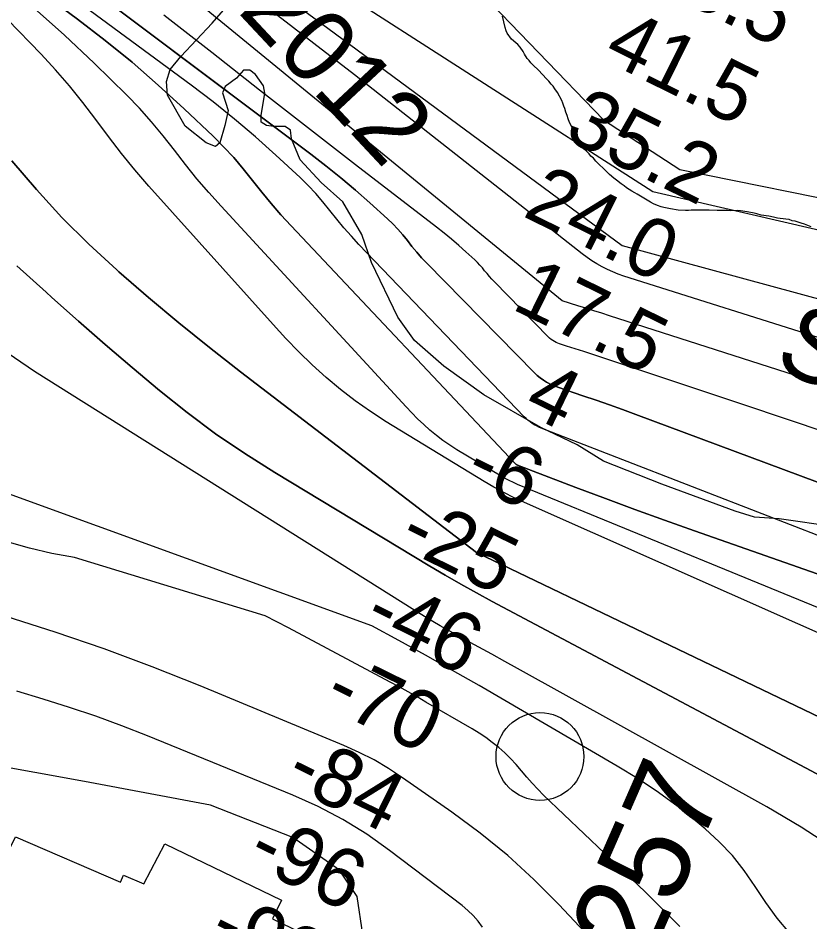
# Model space of a CAD drawing. Extents: x 3263578 to 3301413, y 764927 to 798602.
# Drawn here: x 3281967 to 3282869, y 784025 to 785055 of the extents above; entities that cross this region are included whole.
import ezdxf

# ---------------------------------------------------------------- set-up
doc = ezdxf.new("R2010")
doc.units = 0
for name, color, linetype in [('V-RIVR-EDGE', 7, 'Continuous'), ('V-RIVR-IDEN', 7, 'Continuous'), ('V-RIVR-MILE', 7, 'Continuous'), ('V-RIVR-RANG', 7, 'Continuous'), ('V-RRAP-RVMT', 7, 'Continuous'), ('V-SITE-VEGE', 7, 'Continuous'), ('V-TOPO-DPTH', 7, 'Continuous'), ('V-TOPO-MAJR', 7, 'Continuous'), ('V-TOPO-MINR', 7, 'Continuous'), ('V-TOPO-WATR', 7, 'Continuous')]:
    doc.layers.add(name, color=color, linetype=linetype)

msp = doc.modelspace()

# ---------------------------------------------------------------- linework, layer by layer
at = {"layer": 'V-RIVR-EDGE'}
msp.add_lwpolyline([(3282896.9, 784475.3), (3282833.4, 784484.6), (3282805.6, 784486.4), (3282783.5, 784493), (3282700.1, 784524), (3282633.6, 784550.3), (3282603.7, 784568.6), (3282562, 784588.3), (3282497.3, 784625.8), (3282451.8, 784658.5), (3282418.4, 784687.7), (3282399.3, 784714.3), (3282369.5, 784776.5), (3282358.3, 784808.3), (3282336.6, 784845.7), (3282311.9, 784867.5), (3282288, 784893.2), (3282278.1, 784917.2), (3282277.3, 784927.2), (3282271.2, 784931.5), (3282258.1, 784931.5), (3282249.9, 784932.4), (3282243.8, 784936.4), (3282243.8, 784943.8), (3282247.8, 784969.4), (3282246.5, 784977.7), (3282237.4, 784990.7), (3282230.9, 784995.5), (3282223.5, 784995.5), (3282215.7, 784986.4), (3282202.6, 784976.9), (3282199.6, 784969.5), (3282206, 784949.5), (3282202.5, 784932.6), (3282196.8, 784912.6), (3282191.6, 784908.7), (3282181.2, 784912.6), (3282157.3, 784931.8), (3282137, 784967.1), (3282136.1, 784982.7), (3282140.1, 784996.2), (3282152.3, 785010.9), (3282188, 785049.1), (3282216.8, 785082.5)], dxfattribs=at)
at = {"layer": 'V-RIVR-MILE'}
msp.add_circle((3282561.2, 784213.7), 50, dxfattribs=at)
at = {"layer": 'V-RRAP-RVMT'}
msp.add_lwpolyline([(3281527, 784176.8), (3281659.2, 784111.8), (3281678.1, 784148.8), (3281803, 784083.6), (3281841.2, 784155.5), (3281953.1, 784099.7), (3281963.9, 784122.4), (3282083.6, 784070.4), (3282087.1, 784078.4), (3282110.2, 784068.8), (3282133.9, 784114.1), (3282266.9, 784050.1), (3282256.8, 784028.8), (3282374.6, 783971.7), (3282287.6, 783777.8), (3282370.5, 783940), (3282499.2, 783875.4), (3282489.6, 783855.9)], dxfattribs=at)
at = {"layer": 'V-SITE-VEGE'}
for points in [[(3282598.1, 784929.3), (3282595, 784936), (3282593.3, 784940.1), (3282592, 784944), (3282590.5, 784947.6), (3282589.6, 784951.7), (3282588.4, 784954.5), (3282587.3, 784958), (3282586.2, 784960.9), (3282581.1, 784969.9), (3282578.2, 784974.2), (3282576.1, 784977.1), (3282573.9, 784979.5), (3282571.2, 784983), (3282568.8, 784985.7), (3282559.4, 784995.4), (3282553.5, 785001.2), (3282550.9, 785003.9), (3282548.8, 785006.4), (3282546.8, 785008.9), (3282543.5, 785013.8), (3282542.2, 785016.6), (3282538.5, 785021.8), (3282536.1, 785024.7), (3282533.7, 785026.7), (3282528.8, 785030.7), (3282523.9, 785037.5), (3282522.8, 785040.3), (3282521.7, 785044), (3282518.4, 785057)], [(3282869.9, 784817.1), (3282862.5, 784820), (3282858.7, 784821.3), (3282851.7, 784823.3), (3282848.4, 784823.9), (3282844.9, 784825.4), (3282841, 784825.7), (3282831.8, 784826.8), (3282827.2, 784827.9), (3282821.7, 784829.1), (3282813.1, 784830.5), (3282808.3, 784832), (3282805.3, 784832.7), (3282797.1, 784834.3), (3282789.6, 784835.3), (3282786.6, 784835.6), (3282777.7, 784835.4), (3282774.7, 784835.7), (3282770.3, 784835.8), (3282762.8, 784835.6), (3282753.9, 784836.2), (3282750.5, 784836.1), (3282746.7, 784836.2), (3282743.6, 784835.9), (3282740, 784836.1), (3282736.8, 784836.2), (3282733.5, 784835.9), (3282730.3, 784835.8), (3282726.9, 784835.5), (3282718.4, 784836.1), (3282710, 784837.5), (3282702.3, 784839.1), (3282699.1, 784840), (3282694.9, 784841.5), (3282690.6, 784843.4), (3282687.2, 784845.1), (3282683.4, 784847.3), (3282675.8, 784851.9), (3282671.9, 784854.2), (3282669.3, 784855.9), (3282665.7, 784857.8), (3282659.9, 784861.6), (3282657, 784863.9), (3282653.6, 784866), (3282648.2, 784870.1), (3282645.5, 784872.6), (3282640.3, 784876.8), (3282637.4, 784879.5), (3282625, 784891.9), (3282622, 784895.2), (3282619.3, 784897.5), (3282617.1, 784900), (3282614, 784903.3), (3282611.6, 784905.5), (3282609.3, 784909.2), (3282604.6, 784915.2), (3282602.1, 784918.9), (3282600.5, 784922.2), (3282598.1, 784929.3)]]:
    msp.add_lwpolyline(points, dxfattribs=at)
at = {"layer": 'V-TOPO-DPTH'}
for p, q in [((3282586.3, 784732.7), (3282130.2, 785106.3)), ((3282604.4, 784727.2), (3282586.3, 784732.7)), ((3282622.5, 784721.5), (3282613.5, 784724.3)), ((3283338.4, 784490.7), (3282640.5, 784715.8))]:
    msp.add_line(p, q, dxfattribs=at)
for points in [[(3281734.1, 785325.1), (3282300.2, 784899.9), (3282317.4, 784886.5), (3282334.5, 784872.8), (3282351.1, 784858.7), (3282367.5, 784844.2), (3282387.4, 784826.2), (3282393.5, 784820.3), (3282399.3, 784814.3), (3282404.9, 784807.9), (3282410.2, 784801.3), (3282415.4, 784794.7), (3282420.8, 784788.2), (3282426.4, 784781.9), (3282432.2, 784775.8), (3282554.9, 784650.7), (3282558.1, 784647.7), (3282561.5, 784644.9), (3282565.1, 784642.4), (3282568.8, 784640.2), (3282575.1, 784636.8), (3282575.9, 784636.4), (3282576.6, 784636), (3282577.4, 784635.8), (3282578.3, 784635.5), (3282579.1, 784635.3), (3282579.9, 784635), (3282580.7, 784634.8), (3282581.5, 784634.5), (3282610.1, 784624.7), (3282625.2, 784619.5), (3282640.2, 784614.2), (3282655.2, 784608.8), (3282670.2, 784603.3), (3283436.9, 784317.6)], [(3281761.4, 785255.1), (3282034.4, 785053.5), (3282065.9, 785029.4), (3282096.7, 785004.5), (3282126.6, 784978.4), (3282155.9, 784951.6), (3282189, 784920.2), (3282200.9, 784908.2), (3282212.5, 784895.9), (3282223.4, 784883.1), (3282234, 784869.9), (3282244.4, 784856.6), (3282255.1, 784843.5), (3282266.3, 784830.8), (3282277.7, 784818.3), (3282532.6, 784547.8), (3282532.9, 784547.4), (3282533.3, 784547.1), (3282533.7, 784546.8), (3282534.1, 784546.5), (3282534.5, 784546.3), (3282534.9, 784546), (3282535.4, 784545.8), (3282535.8, 784545.6), (3282602, 784520.3), (3282635.7, 784507.6), (3282669.4, 784495.1), (3282703.1, 784482.9), (3282737, 784470.8), (3283390.2, 784241.8)], [(3283390.2, 784241.8), (3282737, 784470.8), (3282703.1, 784482.9), (3282669.4, 784495.1), (3282635.7, 784507.6), (3282602, 784520.3), (3282535.8, 784545.6), (3282535.4, 784545.8), (3282534.9, 784546), (3282534.5, 784546.3), (3282534.1, 784546.5), (3282533.7, 784546.8), (3282533.3, 784547.1), (3282532.9, 784547.4), (3282532.6, 784547.8), (3282277.7, 784818.3), (3282266.3, 784830.8), (3282255.1, 784843.5), (3282244.4, 784856.6), (3282234, 784869.9), (3282223.4, 784883.1), (3282212.5, 784895.9), (3282200.9, 784908.2), (3282189, 784920.2), (3282155.9, 784951.6), (3282126.6, 784978.4), (3282096.7, 785004.5), (3282065.9, 785029.4), (3282034.4, 785053.5), (3281761.4, 785255.1)], [(3281984.1, 785137.3), (3282300.2, 784899.9), (3282317.4, 784886.5), (3282334.5, 784872.8), (3282351.1, 784858.7), (3282367.5, 784844.2), (3282387.4, 784826.2), (3282393.5, 784820.3), (3282399.3, 784814.3), (3282404.9, 784807.9), (3282410.2, 784801.3), (3282415.4, 784794.7), (3282420.8, 784788.2), (3282426.4, 784781.9), (3282432.2, 784775.8), (3282554.9, 784650.7), (3282558.1, 784647.7), (3282561.5, 784644.9), (3282565.1, 784642.4), (3282568.8, 784640.2), (3282575.1, 784636.8), (3282575.9, 784636.4), (3282576.6, 784636), (3282577.4, 784635.8), (3282578.3, 784635.5), (3282579.1, 784635.3), (3282579.9, 784635), (3282580.7, 784634.8), (3282581.5, 784634.5), (3282610.1, 784624.7), (3282625.2, 784619.5), (3282640.2, 784614.2), (3282655.2, 784608.8), (3282670.2, 784603.3), (3283436.9, 784317.6)], [(3282932.6, 784330.1), (3282543.4, 784502.9), (3282531.7, 784508.5), (3282520.1, 784514.3), (3282508.7, 784520.5), (3282497.5, 784527.1), (3282386.2, 784595.1), (3282368.3, 784606.7), (3282350.9, 784618.9), (3282334.1, 784631.9), (3282317.7, 784645.6), (3282301.9, 784660), (3282286.5, 784674.7), (3282271.7, 784690), (3282257.2, 784705.6), (3282115.9, 784863.5), (3282100, 784881.9), (3282084.5, 784900.6), (3282069.7, 784919.8), (3282055.3, 784939.3), (3282040.7, 784958.7), (3282025.6, 784977.7), (3282009.7, 784996), (3281993.1, 785013.7), (3281954.8, 785053.1)], [(3282932.6, 784330.1), (3282543.4, 784502.9), (3282531.7, 784508.5), (3282520.1, 784514.3), (3282508.7, 784520.5), (3282497.5, 784527.1), (3282386.2, 784595.1), (3282368.3, 784606.7), (3282350.9, 784618.9), (3282334.1, 784631.9), (3282317.7, 784645.6), (3282301.9, 784660), (3282286.5, 784674.7), (3282271.7, 784690), (3282257.2, 784705.6), (3282115.9, 784863.5), (3282100, 784881.9), (3282084.5, 784900.6), (3282069.7, 784919.8), (3282055.3, 784939.3), (3282040.7, 784958.7), (3282025.6, 784977.7), (3282009.7, 784996), (3281993.1, 785013.7), (3281954.8, 785053.1)], [(3281959.7, 784892.1), (3281987.8, 784859.4), (3282016.9, 784827.6), (3282047.6, 784797.3), (3282079.2, 784768), (3282081.7, 784765.8), (3282115.6, 784736.5), (3282150, 784707.7), (3282184.9, 784679.6), (3282220.2, 784652), (3282489, 784446.1), (3283292.2, 784060.3), (3283318.6, 784047.5), (3283344.8, 784034.4)], [(3281959.7, 784892.1), (3281987.8, 784859.4), (3282016.9, 784827.6), (3282047.6, 784797.3), (3282079.2, 784768), (3282081.7, 784765.8), (3282115.6, 784736.5), (3282150, 784707.7), (3282184.9, 784679.6), (3282220.2, 784652), (3282489, 784446.1), (3283292.2, 784060.3), (3283318.6, 784047.5), (3283344.8, 784034.4)], [(3283179.7, 784022.8), (3283158.9, 784037.8), (3283137.5, 784051.9), (3283115.5, 784065.2), (3283093.3, 784078.2), (3283070.8, 784090.7), (3283048.2, 784103), (3282506.9, 784390.4), (3282488.9, 784400.1), (3282471, 784410), (3282453.3, 784420.3), (3282435.7, 784430.7), (3282259.4, 784537.1), (3282225.3, 784558.8), (3282191.9, 784581.4), (3282159.5, 784605.6), (3282127.8, 784630.7), (3282096.9, 784656.7), (3282066.1, 784683), (3282035.7, 784709.6), (3282005.5, 784736.5), (3281998.8, 784742.6), (3281965.4, 784772.8)], [(3281965.4, 784772.8), (3281998.8, 784742.6), (3282005.5, 784736.5), (3282035.7, 784709.6), (3282066.1, 784683), (3282096.9, 784656.7), (3282127.8, 784630.7), (3282159.5, 784605.6), (3282191.9, 784581.4), (3282225.3, 784558.8), (3282259.4, 784537.1), (3282435.7, 784430.7), (3282453.3, 784420.3), (3282471, 784410), (3282488.9, 784400.1), (3282506.9, 784390.4), (3283048.2, 784103), (3283070.8, 784090.7), (3283093.3, 784078.2), (3283115.5, 784065.2), (3283137.5, 784051.9), (3283158.9, 784037.8), (3283179.7, 784022.8)]]:
    msp.add_lwpolyline(points, dxfattribs=at)
at = {"layer": 'V-TOPO-MAJR'}
for points in [[(3280955.5, 789209.2), (3281961, 788391.5), (3282471.7, 787832.1), (3282972.1, 787293.3), (3283564.2, 786549.4), (3284187.3, 785938.5), (3284963.7, 785173.7), (3285326.4, 784855.4), (3285444, 784768), (3285725.2, 784613.8), (3285781.4, 784557.3), (3285781.2, 784480.5), (3285755.4, 784408.9), (3285719.5, 784373.1), (3285678.4, 784342.5), (3285606.7, 784332.4), (3284526.7, 784458), (3283539, 784660.1), (3282689.6, 784856.8), (3282306.2, 785103.5), (3281841.1, 785457.9)], [(3283607.3, 783140.4), (3283032, 783990.3), (3283013.7, 784011.9), (3282993.3, 784032), (3282968.3, 784053.3), (3282933, 784081.7), (3282896.6, 784108.6), (3282858.7, 784133.2), (3282819.7, 784156.4), (3282535.8, 784313.8), (3282521.1, 784321.9), (3282506.3, 784330.1), (3282491.5, 784338.1), (3282476.7, 784346.2), (3282462, 784354.4), (3282447.4, 784362.7), (3282432.9, 784371.4), (3282418.6, 784380.2), (3281985.6, 784652.4), (3281939.5, 784683.5)], [(3282227.2, 783780.1), (3282315.8, 783864), (3282359.5, 783954.1), (3282359.6, 784010.9), (3282353, 784054.3), (3282333.1, 784084.4), (3282279.7, 784121.3), (3282186.2, 784158.3), (3282042.7, 784185.4), (3281929.1, 784205.7), (3281792.2, 784232.8), (3281702, 784236.3), (3281655.3, 784249.8), (3281618.6, 784256.6), (3281568.5, 784273.4), (3281472.5, 784307.7)]]:
    msp.add_lwpolyline(points, dxfattribs=at)
at = {"layer": 'V-TOPO-MINR'}
for p, q in [((3282586.3, 784732.7), (3282130.2, 785106.3)), ((3282350.1, 784990.1), (3282257.5, 785061.4)), ((3282609.4, 784786.2), (3282350.1, 784990.1)), ((3282614.9, 784782.1), (3282609.4, 784786.2)), ((3282620.4, 784778.3), (3282614.9, 784782.1)), ((3282626.1, 784774.8), (3282620.4, 784778.3)), ((3282632, 784771.4), (3282626.1, 784774.8)), ((3282638, 784768.4), (3282632, 784771.4)), ((3282644.2, 784765.6), (3282638, 784768.4)), ((3282650.4, 784763.2), (3282644.2, 784765.6)), ((3282656.8, 784761), (3282650.4, 784763.2)), ((3283204.1, 784587.6), (3282656.8, 784761)), ((3282604.4, 784727.2), (3282586.3, 784732.7)), ((3282613.5, 784724.3), (3282604.4, 784727.2)), ((3282622.5, 784721.5), (3282613.5, 784724.3)), ((3282631.5, 784718.6), (3282622.5, 784721.5)), ((3282640.5, 784715.8), (3282631.5, 784718.6)), ((3283338.4, 784490.7), (3282640.5, 784715.8))]:
    msp.add_line(p, q, dxfattribs=at)
for points in [[(3280773.6, 787080.7), (3280825.2, 786788.5), (3280989.8, 786138.8), (3281113.7, 785969.3), (3281498.4, 785695.6), (3281772.4, 785433.2), (3281863.9, 785380), (3282654.8, 784795.9), (3284438.9, 784310.8), (3284897.9, 784262.5), (3285627.4, 784239.2), (3285928, 784290), (3286001.1, 784358.4), (3286031.3, 784422.7), (3286040, 784465.6), (3286031.5, 784508.6), (3286001.5, 784534.4), (3285915.8, 784577.5), (3285714.3, 784642.4), (3285422.9, 784814.8), (3284904.7, 785270.9), (3284121.3, 786032.5), (3283569.1, 786587.4), (3283000.1, 787318.4)], [(3280798.8, 787096.9), (3281454.2, 786344.7), (3282082.5, 785744.1), (3282128.4, 785662), (3282265.9, 785390.3), (3282485.4, 785092.8), (3282633.5, 784938.8), (3282720.4, 784882.3), (3283155.4, 784794.2), (3283488, 784716.6)], [(3283390.2, 784241.8), (3282737, 784470.8), (3282703.1, 784482.9), (3282669.4, 784495.1), (3282635.7, 784507.6), (3282602, 784520.3), (3282535.8, 784545.6), (3282535.4, 784545.8), (3282534.9, 784546), (3282534.5, 784546.3), (3282534.1, 784546.5), (3282533.7, 784546.8), (3282533.3, 784547.1), (3282532.9, 784547.4), (3282532.6, 784547.8), (3282277.7, 784818.3), (3282266.3, 784830.8), (3282255.1, 784843.5), (3282244.4, 784856.6), (3282234, 784869.9), (3282223.4, 784883.1), (3282212.5, 784895.9), (3282200.9, 784908.2), (3282189, 784920.2), (3282155.9, 784951.6), (3282126.6, 784978.4), (3282096.7, 785004.5), (3282065.9, 785029.4), (3282034.4, 785053.5), (3281761.4, 785255.1)], [(3283252, 784320.5), (3282562.6, 784587.8), (3282559.9, 784588.9), (3282557.3, 784590.2), (3282554.7, 784591.6), (3282552.2, 784593.1), (3282549.9, 784594.8), (3282547.6, 784596.6), (3282545.4, 784598.6), (3282543.3, 784600.6), (3282355, 784797.1), (3282346.4, 784806.4), (3282338, 784815.9), (3282329.9, 784825.6), (3282322.1, 784835.6), (3282314.1, 784845.5), (3282305.9, 784855.1), (3282297.1, 784864.2), (3282288.1, 784873.1), (3282260.6, 784898.5), (3282237.3, 784919.4), (3282213.5, 784939.8), (3282189, 784959.4), (3282164, 784978.4), (3281782.4, 785259.4)], [(3283083.9, 784298.8), (3282535.8, 784523.6), (3282531, 784525.7), (3282526.3, 784528), (3282521.6, 784530.4), (3282517, 784533), (3282466.5, 784563.1), (3282458.5, 784568.2), (3282450.7, 784573.5), (3282443.2, 784579.3), (3282435.9, 784585.4), (3282428.8, 784591.8), (3282421.9, 784598.3), (3282415.2, 784605), (3282408.7, 784611.9), (3282198, 784840.5), (3282184.1, 784856), (3282170.6, 784871.8), (3282157.7, 784888), (3282145, 784904.5), (3282132.3, 784920.8), (3282119, 784936.8), (3282105.1, 784952.1), (3282090.6, 784967), (3282053.7, 785003.3), (3282019.9, 785035.2), (3281985.2, 785066.2)], [(3282889.3, 784582), (3282793.3, 784614.3), (3282611, 784675.1), (3282606.1, 784676.7), (3282601.2, 784678.2), (3282596.3, 784679.7), (3282591.3, 784681.2), (3282585.7, 784682.9), (3282583.6, 784683.6), (3282581.6, 784684.4), (3282579.5, 784685.3), (3282577.6, 784686.4), (3282575.7, 784687.5), (3282573.9, 784688.8), (3282572.2, 784690.2), (3282570.6, 784691.7), (3282509.3, 784754.2), (3282506.4, 784757.3), (3282503.6, 784760.5), (3282500.9, 784763.7), (3282498.2, 784767), (3282495.6, 784770.3), (3282492.8, 784773.5), (3282489.9, 784776.5), (3282486.9, 784779.5), (3282476.9, 784788.5), (3282468.7, 784795.7), (3282460.4, 784802.8), (3282452, 784809.8), (3282443.4, 784816.5), (3282351.1, 784887.8), (3282296.4, 784930.2), (3282241.8, 784972.7), (3282187.4, 785015.5), (3282133, 785058.3)], [(3282932.6, 784330.1), (3282543.4, 784502.9), (3282531.7, 784508.5), (3282520.1, 784514.3), (3282508.7, 784520.5), (3282497.5, 784527.1), (3282386.2, 784595.1), (3282368.3, 784606.7), (3282350.9, 784618.9), (3282334.1, 784631.9), (3282317.7, 784645.6), (3282301.9, 784660), (3282286.5, 784674.7), (3282271.7, 784690), (3282257.2, 784705.6), (3282115.9, 784863.5), (3282100, 784881.9), (3282084.5, 784900.6), (3282069.7, 784919.8), (3282055.3, 784939.3), (3282040.7, 784958.7), (3282025.6, 784977.7), (3282009.7, 784996), (3281993.1, 785013.7), (3281954.8, 785053.1)], [(3283344.8, 784034.4), (3283318.6, 784047.5), (3283292.2, 784060.3), (3282489, 784446.1), (3282220.2, 784652), (3282184.9, 784679.6), (3282150, 784707.7), (3282115.6, 784736.5), (3282081.7, 784765.8), (3282079.2, 784768), (3282047.6, 784797.3), (3282016.9, 784827.6), (3281987.8, 784859.4), (3281959.7, 784892.1)], [(3283179.7, 784022.8), (3283158.9, 784037.8), (3283137.5, 784051.9), (3283115.5, 784065.2), (3283093.3, 784078.2), (3283070.8, 784090.7), (3283048.2, 784103), (3282506.9, 784390.4), (3282488.9, 784400.1), (3282471, 784410), (3282453.3, 784420.3), (3282435.7, 784430.7), (3282259.4, 784537.1), (3282225.3, 784558.8), (3282191.9, 784581.4), (3282159.5, 784605.6), (3282127.8, 784630.7), (3282096.9, 784656.7), (3282066.1, 784683), (3282035.7, 784709.6), (3282005.5, 784736.5), (3281998.8, 784742.6), (3281965.4, 784772.8)], [(3282845.2, 784012.8), (3282831.2, 784029.7), (3282818.3, 784047.4), (3282806.2, 784065.7), (3282793.8, 784083.7), (3282780.3, 784100.8), (3282765.2, 784116.6), (3282749.2, 784131.4), (3282740.2, 784139), (3282718.4, 784156.3), (3282696, 784172.8), (3282672.9, 784188.2), (3282649.2, 784202.8), (3282491.8, 784294.4), (3282461.5, 784311.8), (3282431, 784329), (3282400.4, 784345.9), (3282369.7, 784362.5), (3281428.1, 784704.7)], [(3282720.6, 784020), (3282700.9, 784039.9), (3282680.9, 784059.5), (3282565.3, 784169.8), (3282558.6, 784176.4), (3282552.2, 784183.2), (3282546.1, 784190.2), (3282540.1, 784197.4), (3282540, 784197.4), (3282534, 784204.5), (3282527.8, 784211.3), (3282521.1, 784217.8), (3282514.2, 784223.9), (3282506.9, 784229.7), (3282499.5, 784235.2), (3282491.8, 784240.3), (3282483.9, 784245.2), (3282431.4, 784275.7), (3282421.3, 784281.5), (3282411.2, 784287.3), (3282401, 784292.9), (3282390.7, 784298.4), (3282274.9, 784360.3), (3282248.2, 784373.9), (3282031.3, 784440.3), (3282005.5, 784445.1), (3281980, 784451.2), (3281954.6, 784458.1)], [(3282618, 784007.7), (3282582.8, 784045), (3282554.2, 784073.5), (3282524.5, 784100.8), (3282493.1, 784126.3), (3282460.7, 784150.4), (3282404.8, 784189.5), (3282388.7, 784200), (3282372.3, 784209.8), (3282355.2, 784218.4), (3282337.7, 784226.3), (3282174.3, 784294.1), (3282119.7, 784315.7), (3282064.8, 784336.3), (3282009.3, 784355.3), (3281953.4, 784373.1)], [(3282495.9, 784019.2), (3282490.8, 784026.1), (3282485.3, 784032.5), (3282479.2, 784038.4), (3282472.6, 784044), (3282390, 784106.8), (3282363.9, 784125.1), (3282336.9, 784141.9), (3282308.7, 784156.6), (3282279.6, 784169.8), (3282114.3, 784237.3), (3282085, 784248.7), (3282055.5, 784259.6), (3282025.6, 784269.7), (3281995.6, 784279.2), (3281965.4, 784288.3)]]:
    msp.add_lwpolyline(points, dxfattribs=at)
at = {"layer": 'V-TOPO-WATR'}
msp.add_lwpolyline([(3283436.9, 784317.6), (3282670.2, 784603.3), (3282655.2, 784608.8), (3282640.2, 784614.2), (3282625.2, 784619.5), (3282610.1, 784624.7), (3282581.5, 784634.5), (3282580.7, 784634.8), (3282579.9, 784635), (3282579.1, 784635.3), (3282578.3, 784635.5), (3282577.4, 784635.8), (3282576.6, 784636), (3282575.9, 784636.4), (3282575.1, 784636.8), (3282568.8, 784640.2), (3282565.1, 784642.4), (3282561.5, 784644.9), (3282558.1, 784647.7), (3282554.9, 784650.7), (3282432.2, 784775.8), (3282426.4, 784781.9), (3282420.8, 784788.2), (3282415.4, 784794.7), (3282410.2, 784801.3), (3282404.9, 784807.9), (3282399.3, 784814.3), (3282393.5, 784820.3), (3282387.4, 784826.2), (3282367.5, 784844.2), (3282351.1, 784858.7), (3282334.5, 784872.8), (3282317.4, 784886.5), (3282300.2, 784899.9), (3281734.1, 785325.1)], dxfattribs=at)

# ---------------------------------------------------------------- texts
at = {"layer": 'V-RIVR-IDEN'}
for s, height, rotation, p in [(' 2012', 83, 313.0908, (3282195, 785084.5)), ('Sand Bar', 83, 335.0627, (3282825.3, 784658.7)), ('257', 100, 66.3774, (3282683.7, 783974))]:
    msp.add_text(s, height=height, rotation=rotation, dxfattribs=at).set_placement(p)
at = {"layer": 'V-RIVR-RANG'}
for s, rotation, p in [('38.5', 333.5983, (3282675.4, 785097.7)), ('41.5', 333.5983, (3282631.2, 785008)), ('35.2', 333.5983, (3282586.9, 784918.3)), ('24.0', 333.5983, (3282540.1, 784829.9)), ('17.5', 333.8079, (3282527.5, 784724.2)), ('4', 333.8079, (3282540.3, 784606.5)), ('-6', 333.8079, (3282472.1, 784528.6)), ('-25', 333.8079, (3282397.6, 784453.8)), ('-46', 333.8079, (3282357.6, 784362)), ('-70', 333.8079, (3282312.1, 784272.9)), ('-84', 333.8079, (3282268.3, 784183)), ('-96', 333.8079, (3282224.8, 784093)), ('-99', 333.8079, (3282180.8, 784003.2))]:
    msp.add_text(s, height=67, rotation=rotation, dxfattribs=at).set_placement(p)

doc.saveas('drawing.dxf')
